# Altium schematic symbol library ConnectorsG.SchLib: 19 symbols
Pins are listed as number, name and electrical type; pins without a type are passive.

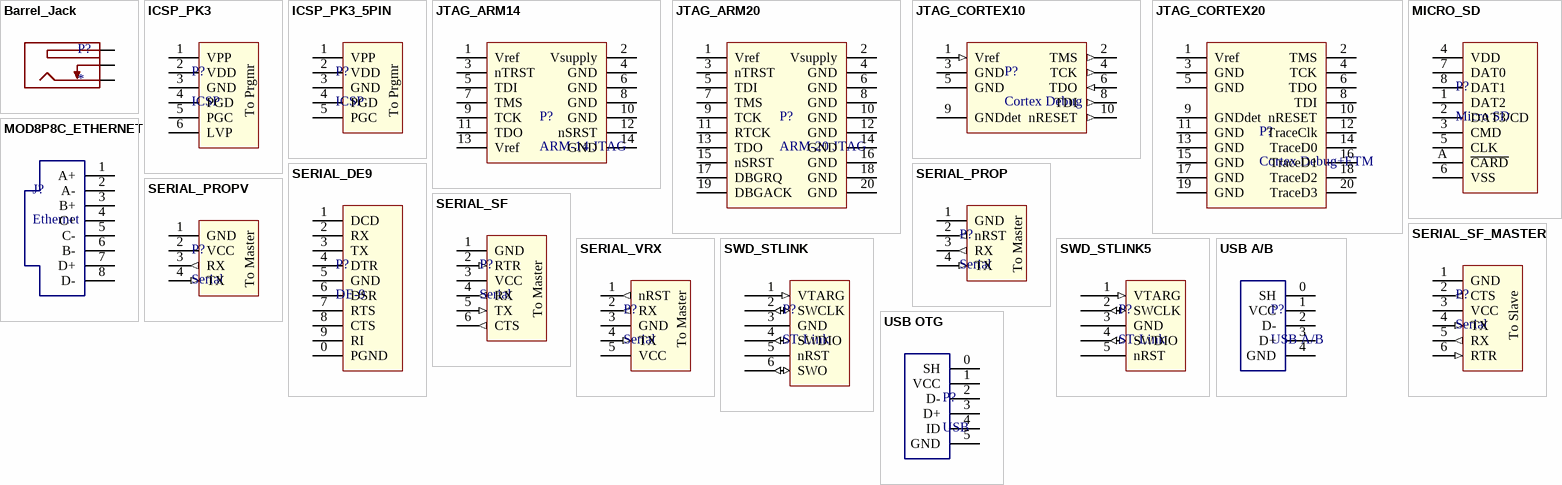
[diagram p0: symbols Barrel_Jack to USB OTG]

## Barrel_Jack
designator P?
DC Power Jack - Barrel Type
footprint PJ-002A (DC Power Jack - Barrel Type)
footprint PJ-007 (Power Jack 1.3mm ID, 3.5mm OD)
pins: RING, SWITCH, TIP

## ICSP_PK3
designator P?, comment ICSP
PICKit3 compatible ICSP header
footprint HDR1X6 (Footprint not found)
pins: 1 VPP, 2 VDD, 3 GND, 4 PGD, 5 PGC, 6 LVP

## ICSP_PK3_5PIN
designator P?, comment ICSP
PICKit3 compatible ICSP header
footprint HDR1X5 (Connector; Header; 5 Position)
pins: 1 VPP, 2 VDD, 3 GND, 4 PGD, 5 PGC

## JTAG_ARM14
designator P?, comment ARM-14 JTAG
JTAG - ARM 14-pin style
footprint HDR2X7 (Connector; Header; 7x2 Position)
pins: 1 Vref, 2 Vsupply, 3 nTRST, 4 GND, 5 TDI, 6 GND, 7 TMS, 8 GND, 9 TCK, 10 GND, 11 TDO, 12 nSRST, 13 Vref, 14 GND

## JTAG_ARM20
designator P?, comment ARM-20 JTAG
JTAG - ARM 20-pin style
footprint HDR2X10 (Connector; Header; 10x2 Position)
pins: 1 Vref, 2 Vsupply, 3 nTRST, 4 GND, 5 TDI, 6 GND, 7 TMS, 8 GND, 9 TCK, 10 GND, 11 RTCK, 12 GND, 13 TDO, 14 GND, 15 nSRST, 16 GND, 17 DBGRQ, 18 GND, 19 DBGACK, 20 GND

## JTAG_CORTEX10
designator P?, comment Cortex Debug
JTAG - ARM Cortex Debug
pins: 1 Vref (in), 2 TMS (out), 3 GND, 4 TCK (out), 5 GND, 6 TDO (in), 8 TDI (out), 9 GNDdet, 10 nRESET (out)

## JTAG_CORTEX20
designator P?, comment Cortex Debug+ETM
JTAG - ARM Cortex Debug+ETM
pins: 1 Vref, 2 TMS, 3 GND, 4 TCK, 5 GND, 6 TDO, 8 TDI, 9 GNDdet, 10 nRESET, 11 GND, 12 TraceClk, 13 GND, 14 TraceD0, 15 GND, 16 TraceD1, 17 GND, 18 TraceD2, 19 GND, 20 TraceD3

## MICRO_SD
designator P?, comment Micro SD
pins: 1 DAT2, 2 DAT3/CD, 3 CMD, 4 VDD, 5 CLK, 6 VSS, 7 DAT0, 8 DAT1, A ~{CARD}

## MOD8P8C_ETHERNET
designator J?, comment Ethernet
8p8c connector for Ethernet
pins: 1 A+, 2 A-, 3 B+, 4 C+, 5 C-, 6 B-, 7 D+, 8 D-

## SERIAL_DE9
designator P?, comment DE-9
DE-9 connector for RS-232
pins: 0 PGND, 1 DCD, 2 RX, 3 TX, 4 DTR, 5 GND, 6 DSR, 7 RTS, 8 CTS, 9 RI

## SERIAL_PROP
designator P?, comment Serial
"Prop Clip"-compatible serial
footprint HDR1X4 (Connector; Header; 4 Position)
pins: 1 GND (power), 2 nRST (out), 3 RX (out), 4 TX (in)

## SERIAL_PROPV
designator P?, comment Serial
Prop-Clip variant with VCC
footprint HDR1X4 (Connector; Header; 4 Position)
pins: 1 GND (power), 2 VCC (power), 3 RX (out), 4 TX (in)

## SERIAL_SF
designator P?, comment Serial
Sparkfun-compatible serial header for slave device
footprint HDR1X6 (Footprint not found)
pins: 1 GND (power), 2 RTR (in), 3 VCC (power), 4 RX (out), 5 TX (in), 6 CTS (out)

## SERIAL_SF_MASTER
designator P?, comment Serial
Sparkfun-compatible serial header for master device
footprint HDR1X6 (Footprint not found)
pins: 1 GND (power), 2 CTS (out), 3 VCC (power), 4 TX (in), 5 RX (out), 6 RTR (in)

## SERIAL_VRX
designator P?, comment Serial
Serial with VCC and reset
footprint HDR1X5 (Footprint not found)
pins: 1 nRST (out), 2 RX (out), 3 GND (power), 4 TX (in), 5 VCC

## SWD_STLINK
designator P?, comment ST-Link
footprint HDR1X6 (Footprint not found)
pins: 1 VTARG (in), 2 SWCLK (io), 3 GND (power), 4 SWDIO (io), 5 nRST, 6 SWO (io)

## SWD_STLINK5
designator P?, comment ST-Link
footprint HDR1X5
pins: 1 VTARG (in), 2 SWCLK (io), 3 GND (power), 4 SWDIO (io), 5 nRST

## USB A/B
designator P?
footprint 48037-2200 (USB A Type Plug SMT)
pins: 0 SH, 1 VCC, 2 D-, 3 D+, 4 GND

## USB OTG
designator P?, comment USB
USB OTG
footprint UX60-MB-5ST (USB Mini-AB Receptacle)
pins: 0 SH, 1 VCC, 2 D-, 3 D+, 4 ID, 5 GND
